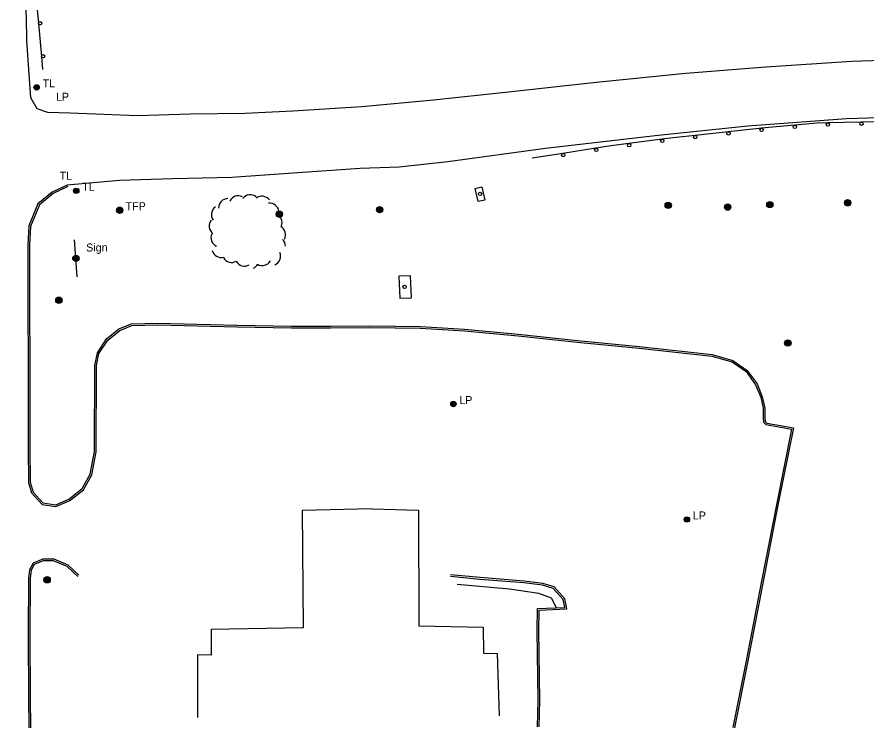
# Model space of a CAD drawing. Extents: x 2402803 to 2427059, y 6985292 to 6997652.
# Drawn here: x 2422741 to 2423250, y 6990856 to 6991282 of the extents above; entities that cross this region are included whole.
import ezdxf

# ---------------------------------------------------------------- set-up
doc = ezdxf.new("R2010")
doc.units = 0
for name, color, linetype in [('p_dtm sidewalk', 7, 'Continuous'), ('p_road - paved curb', 7, 'Continuous'), ('p_road guard rails', 7, 'Continuous'), ('p_structure building', 7, 'Continuous'), ('p_structure general', 7, 'Continuous'), ('p_structure sign', 7, 'Continuous'), ('p_structure slab', 7, 'Continuous'), ('p_utility manhole', 7, 'Continuous'), ('p_veg woods', 7, 'Continuous')]:
    doc.layers.add(name, color=color, linetype=linetype)

msp = doc.modelspace()

# ---------------------------------------------------------------- linework, layer by layer
at = {"layer": 'p_dtm sidewalk'}
msp.add_lwpolyline([(2423064.32, 6990928.32), (2423061.29, 6990934.08), (2423053.73, 6990936.91), (2423036.18, 6990939.41), (2423004.84, 6990942.31)], dxfattribs=at)
at = {"layer": 'p_road - paved curb'}
for points in [[(2422749.46, 6991770.31), (2422747.16, 6991764.46), (2422744.82, 6991750.23), (2422743.04, 6991731.75), (2422741.44, 6991707.72), (2422740.99, 6991691.79), (2422741.09, 6991651.84), (2422741.43, 6991617.57), (2422742.15, 6991583.54), (2422742.75, 6991550.19), (2422742.99, 6991520.78), (2422743.39, 6991492.44), (2422743.81, 6991454.8), (2422744.13, 6991425.61), (2422744.45, 6991392.54), (2422745.06, 6991359.79), (2422745.8, 6991321.9), (2422745.89, 6991290.89), (2422746.51, 6991282.23)], [(2422746.51, 6991282.23), (2422746.74, 6991268.13), (2422748.27, 6991245.03), (2422749.17, 6991233.99), (2422752.84, 6991227.41), (2422759.21, 6991225.23), (2422772.76, 6991224.76), (2422813.16, 6991223.28), (2422844.97, 6991224.28), (2422877.52, 6991224.58), (2422906.34, 6991226.03), (2422947.6, 6991228.61)], [(2422947.6, 6991228.61), (2422990.63, 6991232.66), (2423035.53, 6991237.45), (2423088.04, 6991243.18), (2423141.83, 6991248.63), (2423189.85, 6991252.47), (2423241.37, 6991255.86), (2423294.98, 6991257.65), (2423370.58, 6991257.49), (2423440.96, 6991257.56), (2423519.39, 6991256.91), (2423583.08, 6991256.39), (2423655.59, 6991256.03), (2423711.57, 6991255.63), (2423769.8, 6991255.03), (2423819.23, 6991254.49), (2423892.66, 6991254.22), (2423949.43, 6991253.19), (2424011.2, 6991252.67), (2424055.37, 6991251.98), (2424091.97, 6991251.79)], [(2424092.52, 6991219.97), (2424026.21, 6991221.4), (2423967.56, 6991222.32), (2423917.5, 6991222.69), (2423859.49, 6991223.54), (2423794.83, 6991223.99), (2423745.86, 6991225.15), (2423703.49, 6991224.71), (2423673.38, 6991223.52), (2423625.16, 6991221.62), (2423569.7, 6991220.39), (2423512.16, 6991221.26), (2423466.83, 6991222.06), (2423403.91, 6991223.37), (2423357.11, 6991222.6), (2423297.52, 6991223.13), (2423238.16, 6991221.26), (2423179.01, 6991216.95), (2423125.23, 6991211.26), (2423057.81, 6991203.42), (2422999.29, 6991195.56), (2422970.01, 6991192.39), (2422946.68, 6991191.48)], [(2422946.68, 6991191.48), (2422906.58, 6991188.7), (2422869.82, 6991186.06), (2422834.18, 6991185.22), (2422802.38, 6991184.25), (2422771.1, 6991181.57)], [(2422771.1, 6991181.57), (2422762.1, 6991177.28), (2422753.55, 6991170.36), (2422748.14, 6991157.06), (2422747.45, 6991145.77), (2422747.46, 6991114.7), (2422747.69, 6991067.89), (2422747.7, 6991024.42), (2422747.87, 6991003.4), (2422749.75, 6990997.07), (2422756.07, 6990990.18), (2422764.31, 6990988.89), (2422772.6, 6990992.5), (2422780.76, 6990999.01), (2422785.86, 6991008.05), (2422788.51, 6991021.79), (2422788.55, 6991073.37), (2422790.13, 6991080.6), (2422795.4, 6991088.69), (2422802.62, 6991094.51), (2422809.82, 6991097.47), (2422825.49, 6991097.89), (2422872.83, 6991096.66), (2422905.6, 6991096.02), (2422928.81, 6991096.11), (2422952.41, 6991096.25)], [(2422771.53, 6991180.67), (2422762.64, 6991176.43), (2422754.38, 6991169.74), (2422749.13, 6991156.84), (2422748.45, 6991145.74), (2422748.46, 6991114.7), (2422748.69, 6991067.89), (2422748.7, 6991024.42), (2422748.87, 6991003.55), (2422750.64, 6990997.58), (2422756.57, 6990991.11), (2422764.18, 6990989.92), (2422772.08, 6990993.36), (2422779.98, 6990999.67), (2422784.91, 6991008.4), (2422787.51, 6991021.89), (2422787.55, 6991073.48), (2422789.19, 6991080.99), (2422794.65, 6991089.37), (2422802.11, 6991095.38), (2422809.61, 6991098.46), (2422825.49, 6991098.89), (2422872.85, 6991097.66), (2422905.61, 6991097.02), (2422928.81, 6991097.11), (2422952.4, 6991097.25)], [(2422952.41, 6991096.25), (2422982.77, 6991095.77), (2423009.18, 6991094.22), (2423041.31, 6991091.27), (2423076.78, 6991087.43), (2423113.82, 6991083.9), (2423157.46, 6991078.99), (2423169.59, 6991075.63), (2423178.01, 6991069.77), (2423183.72, 6991061.92), (2423186.75, 6991054.4), (2423188.27, 6991047.84), (2423188.24, 6991042.13), (2423188.46, 6991039.54), (2423189.92, 6991038.06), (2423205.17, 6991035.23), (2423196.33, 6990990.9), (2423187.12, 6990943.33), (2423177.97, 6990896.6), (2423170.12, 6990856.48)], [(2422952.43, 6991097.25), (2422982.81, 6991096.77), (2423009.26, 6991095.22), (2423041.41, 6991092.27), (2423076.88, 6991088.42), (2423113.92, 6991084.89), (2423157.65, 6991079.97), (2423170.02, 6991076.55), (2423178.72, 6991070.49), (2423184.6, 6991062.41), (2423187.71, 6991054.7), (2423189.27, 6991047.95), (2423189.24, 6991042.17), (2423189.43, 6991039.98), (2423190.41, 6991038.99), (2423206.35, 6991036.03), (2423197.31, 6990990.71), (2423188.1, 6990943.14), (2423178.95, 6990896.41), (2423171.1, 6990856.29)], [(2422778.07, 6990947.82), (2422771.63, 6990953.85), (2422763.17, 6990957.44), (2422756.47, 6990957.51), (2422750.62, 6990954.96), (2422748.42, 6990951.09), (2422747.98, 6990946.2), (2422747.64, 6990912.02), (2422747.87, 6990874.62), (2422747.99, 6990856.27)], [(2422777.39, 6990947.09), (2422771.08, 6990953), (2422762.96, 6990956.44), (2422756.67, 6990956.51), (2422751.32, 6990954.18), (2422749.4, 6990950.78), (2422748.98, 6990946.15), (2422748.64, 6990912.02), (2422748.87, 6990874.63), (2422748.99, 6990856.28)], [(2423052.91, 6990857.02), (2423053.39, 6990872.94), (2423052.86, 6990914.61), (2423052.92, 6990927.86), (2423069.34, 6990928.52), (2423068.44, 6990933.27), (2423062.43, 6990939.93), (2423055.96, 6990941.88), (2423044.88, 6990943.16), (2423018.44, 6990945.34), (2423000.74, 6990946.97)], [(2423053.91, 6990856.99), (2423054.39, 6990872.93), (2423053.86, 6990914.61), (2423053.92, 6990926.9), (2423070.54, 6990927.57), (2423069.37, 6990933.73), (2423062.99, 6990940.81), (2423056.16, 6990942.86), (2423044.98, 6990944.16), (2423018.53, 6990946.34), (2423000.83, 6990947.97)]]:
    msp.add_lwpolyline(points, dxfattribs=at)
at = {"layer": 'p_road guard rails'}
for p, q in [((2422753.83, 6991278.45), (2422755.65, 6991258.67)), ((2422755.65, 6991258.67), (2422756.37, 6991250.84)), ((2423207.13, 6991217.4), (2423187.22, 6991215.61)), ((2423247.05, 6991219.34), (2423227.06, 6991218.79)), ((2423267.05, 6991219.88), (2423247.05, 6991219.34)), ((2423167.34, 6991213.49), (2423147.46, 6991211.33)), ((2423127.6, 6991209.03), (2423107.78, 6991206.43)), ((2423068.25, 6991200.52), (2423049.74, 6991197.62)), ((2423088, 6991203.6), (2423068.25, 6991200.52))]:
    msp.add_line(p, q, dxfattribs=at)
for points in [[(2422752.64, 6991298.31), (2422752.7, 6991290.76), (2422753.83, 6991278.45)], [(2423187.22, 6991215.61), (2423185.61, 6991215.47), (2423167.34, 6991213.49)], [(2423227.06, 6991218.79), (2423220.7, 6991218.62), (2423207.13, 6991217.4)], [(2423147.46, 6991211.33), (2423134.32, 6991209.91), (2423127.6, 6991209.03)], [(2423107.78, 6991206.43), (2423097.18, 6991205.04), (2423088, 6991203.6)]]:
    msp.add_lwpolyline(points, dxfattribs=at)
for centre in [(2422754.83, 6991278.54), (2422756.65, 6991258.76), (2423187.31, 6991214.62), (2423207.22, 6991216.41), (2423227.09, 6991217.79), (2423247.08, 6991218.34), (2423147.57, 6991210.34), (2423167.45, 6991212.5), (2423107.91, 6991205.44), (2423127.73, 6991208.04), (2423068.41, 6991199.53), (2423088.16, 6991202.62)]:
    msp.add_circle(centre, 1, dxfattribs=at)
at = {"layer": 'p_structure building'}
for points in [[(2422953.87, 6990987.57), (2422911.94, 6990986.53), (2422912.5, 6990916.35), (2422857.4, 6990915.28), (2422857.33, 6990899.96), (2422849.27, 6990900.07), (2422849.14, 6990862.49)], [(2422953.87, 6990987.57), (2422981.61, 6990986.85), (2422981.88, 6990917.42), (2423020.34, 6990916.7), (2423020.67, 6990901.08), (2423028.86, 6990900.98), (2423029.93, 6990863.64)]]:
    msp.add_lwpolyline(points, dxfattribs=at)
at = {"layer": 'p_structure general'}
for centre in [(2423018.53, 6991176.22), (2422973.31, 6991120.5)]:
    msp.add_circle(centre, 1, dxfattribs=at)
at = {"layer": 'p_structure sign'}
msp.add_line((2422777.13, 6991126.63), (2422775.47, 6991148.75), dxfattribs=at)
for radius in [1.9, 1.44, 0.973, 0.539, 0.192]:
    msp.add_circle((2422776.3, 6991137.69), radius, dxfattribs=at)
at = {"layer": 'p_structure slab'}
for points in [[(2423019.51, 6991180.49), (2423021.36, 6991172.54), (2423017.47, 6991171.63), (2423015.62, 6991179.58)], [(2422969.93, 6991126.91), (2422970.44, 6991113.81), (2422977.44, 6991114.08), (2422976.93, 6991127.18)]]:
    msp.add_lwpolyline(points, close=True, dxfattribs=at)
at = {"layer": 'p_utility manhole'}
for centre, radius in [((2422752.77, 6991240.11), 1.6), ((2422752.77, 6991240.11), 1.3), ((2422752.77, 6991240.11), 1), ((2422752.77, 6991240.11), 0.539), ((2422752.77, 6991240.11), 0.192), ((2422776.53, 6991178.13), 1.6), ((2422776.53, 6991178.13), 1.6), ((2422776.53, 6991178.13), 1.3), ((2422776.53, 6991178.13), 1.3), ((2422776.53, 6991178.13), 1), ((2422776.53, 6991178.13), 1), ((2422776.53, 6991178.13), 0.539), ((2422776.53, 6991178.13), 0.539), ((2422776.53, 6991178.13), 0.192), ((2422776.53, 6991178.13), 0.192), ((2423131.3, 6991169.46), 1.9), ((2423131.3, 6991169.46), 1.44), ((2423131.3, 6991169.46), 0.973), ((2423131.3, 6991169.46), 0.539), ((2423131.3, 6991169.46), 0.192), ((2423167, 6991168.37), 1.9), ((2423167, 6991168.37), 1.44), ((2423192.25, 6991169.82), 1.9), ((2423192.25, 6991169.82), 1.44), ((2423192.25, 6991169.82), 0.973), ((2423192.25, 6991169.82), 0.539), ((2423192.25, 6991169.82), 0.192), ((2423238.84, 6991170.96), 1.9), ((2423238.84, 6991170.96), 1.44), ((2423238.84, 6991170.96), 0.973), ((2423238.84, 6991170.96), 0.539), ((2423238.84, 6991170.96), 0.192), ((2422802.5, 6991166.48), 1.9), ((2422802.5, 6991166.48), 1.44), ((2422802.5, 6991166.48), 0.973), ((2422802.5, 6991166.48), 0.539), ((2422802.5, 6991166.48), 0.192), ((2422898.23, 6991164.12), 1.9), ((2422898.23, 6991164.12), 1.44), ((2422898.23, 6991164.12), 0.973), ((2422898.23, 6991164.12), 0.539), ((2422958.35, 6991166.8), 1.9), ((2422958.35, 6991166.8), 1.44), ((2422958.35, 6991166.8), 0.973), ((2422958.35, 6991166.8), 0.539), ((2422958.35, 6991166.8), 0.192), ((2423167, 6991168.37), 0.973), ((2423167, 6991168.37), 0.539), ((2423167, 6991168.37), 0.192), ((2422898.23, 6991164.12), 0.192), ((2422766.1, 6991112.56), 1.9), ((2422766.1, 6991112.56), 1.44), ((2422766.1, 6991112.56), 0.973), ((2422766.1, 6991112.56), 0.539), ((2422766.1, 6991112.56), 0.192), ((2423203.02, 6991086.97), 1.9), ((2423203.02, 6991086.97), 1.44), ((2423203.02, 6991086.97), 0.973), ((2423203.02, 6991086.97), 0.539), ((2423203.02, 6991086.97), 0.192), ((2423002.54, 6991050.35), 1.6), ((2423002.54, 6991050.35), 1.3), ((2423002.54, 6991050.35), 1), ((2423002.54, 6991050.35), 0.539), ((2423002.54, 6991050.35), 0.192), ((2423142.52, 6990981.2), 1.6), ((2423142.52, 6990981.2), 1.3), ((2423142.52, 6990981.2), 1), ((2423142.52, 6990981.2), 0.539), ((2423142.52, 6990981.2), 0.192), ((2422759.04, 6990945.06), 1.9), ((2422759.04, 6990945.06), 1.44), ((2422759.04, 6990945.06), 0.973), ((2422759.04, 6990945.06), 0.539), ((2422759.04, 6990945.06), 0.192)]:
    msp.add_circle(centre, radius, dxfattribs=at)
at = {"layer": 'p_veg woods'}
for centre, start, end in [((2422873.6, 6991169.49), 63.7265, 153.7265), ((2422880.79, 6991170.07), 51.6715, 141.6715), ((2422887.78, 6991169.24), 37.6135, 127.6135), ((2422867.5, 6991167.85), 91.2418, 181.2418), ((2422892.34, 6991165.12), 7.0144, 97.0144), ((2422863.17, 6991163.85), 125.2621, 215.2621), ((2422861.83, 6991157.07), 141.8857, 231.8857), ((2422894.22, 6991159.05), 338.7776, 68.7776), ((2422896.31, 6991151.89), 330.884, 60.884), ((2422862.84, 6991150.13), 156.0898, 246.0898), ((2422896.22, 6991144.94), 0.4603, 45.0977), ((2422863.4, 6991143.83), 194.8162, 284.8162), ((2422893.37, 6991138.99), 292.6383, 22.6383), ((2422869.69, 6991140.87), 209.1319, 299.1319), ((2422877.39, 6991138.68), 209.1319, 299.1319), ((2422880.23, 6991136.9), 296.5694, 330.0016), ((2422887.96, 6991138.97), 240.0016, 330.0016)]:
    msp.add_arc(centre, 5.65, start, end, dxfattribs=at)

# ---------------------------------------------------------------- texts
at = {"layer": 'p_structure sign'}
msp.add_text('Sign', height=4.8, dxfattribs=at).set_placement((2422782.45, 6991141.77))
at = {"layer": 'p_utility manhole'}
for s, p in [('  TL', (2422752.77, 6991240.11)), ('LP', (2422764.34, 6991232.08)), ('  TL', (2422762.98, 6991184.76)), ('  TL', (2422776.53, 6991178.13)), ('  TFP', (2422802.5, 6991166.48)), ('  LP', (2423002.54, 6991050.35)), ('  LP', (2423142.52, 6990981.2))]:
    msp.add_text(s, height=4.8, dxfattribs=at).set_placement(p)

doc.saveas('drawing.dxf')
